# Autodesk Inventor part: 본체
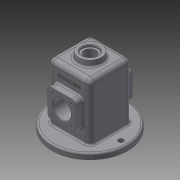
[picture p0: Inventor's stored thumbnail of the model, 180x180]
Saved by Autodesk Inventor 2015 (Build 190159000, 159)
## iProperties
Created: 2021-08
Part Number: 본체
Material: 일반
Document SubType Name: Modeling
Designer: 10415
Density: 1 g/cm^3
Appearance: 기본값
Author: 10415
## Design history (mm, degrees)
sketch "스케치1"
  geometry: C1 r 67 at (0, 0); 1 further point
  constraints: 1 centre point, 1 coincident
  dimensions: "d0" = 134 diameter of C1
extrude "돌출1" new body sketch "스케치1" distance "d1" = 10; taper "d2" = 0 deg
sketch "스케치2"
  geometry: L1 (37, -37)-(-37, -37); L2 (-37, -37)-(-37, 37); L3 (-37, 37)-(37, 37); L4 (37, 37)-(37, -37); L5 (37, -37)-(-37, 37); L6 (-37, -37)-(37, 37); C1 r 67 at (0, 0) reference
  constraints: 12 end point, 2 midpoint, 2 parallel, 1 horizontal, 1 perpendicular
  dimensions: "d3" = 74 distance of L3.end L1.start; "d4" = 74 distance of L2.end L3.end
extrude "돌출2" join sketch "스케치2" distance "d5" = 100; taper "d6" = 0 deg
sketch "스케치3"
  geometry: L1 (32, -32)-(-32, -32); L2 (-32, -32)-(-32, 32); L3 (-32, 32)-(32, 32); L4 (32, 32)-(32, -32); L5 (32, -32)-(-32, 32); L6 (-32, -32)-(32, 32); C1 r 67 at (0, 0) reference
  constraints: 12 end point, 2 midpoint, 2 parallel, 1 horizontal, 1 perpendicular
  dimensions: "d7" = 64 distance of L1.end L2.end; "d8" = 64 distance of L2.end L3.end
extrude "돌출3" cut sketch "스케치3" distance "d9" = 105; taper "d10" = 0 deg
fillet "모깎기2" dims "d27" = 3
node "작업 평면1"
sketch "스케치7"
  geometry: C1 r 20 at (0, 0); 1 further point
  constraints: 1 centre point, 1 coincident
  dimensions: "d29" = 40 diameter of C1
extrude "돌출6" join sketch "스케치7" stored distance "d30" = 13; taper "d31" = 6 deg
sketch "스케치8"
  geometry: C1 r 20 at (0, 0) reference; C2 r 14 at (0, 0)
  constraints: 1 centre point, 1 coincident
  dimensions: "d32" = 28 diameter of C2
extrude "돌출7" cut sketch "스케치8" distance "d33" = 4; taper "d34" = 0 deg
sketch "스케치9"
  geometry: C1 r 14 at (0, 0) reference; C2 r 10.5 at (0, 0)
  constraints: 1 centre point, 1 coincident
  dimensions: "d35" = 21 diameter of C2
extrude "돌출8" cut sketch "스케치9" stored distance "d36" = 4; taper "d37" = 0 deg
fillet "모깎기3" dims "d38" = 8
fillet "모깎기4" dims "d39" = 8
sketch "스케치12"
  geometry: L1 (-38, -10)-(96, -10) reference; C1 r 25 at (29, 45); 1 further point
  constraints: 1 centre point, 1 vertical alignment
  dimensions: "d56" = 50 diameter of C1; "d57" = 55 distance from line of L1 C1.centre
extrude "돌출11" join sketch "스케치12" distance "d58" = 13; taper "d60" = 0 deg; dims "d59" = 12, "d61" = 0
chamfer "모따기2" distance "d62" = 7; stored, may be unused: second distance "d63" = 2, angle "d64" = 20 deg
sketch "스케치13"
  geometry: L1 (-25, -25)-(25, -25); L2 (25, -25)-(25, 25); L3 (25, 25)-(-25, 25); L4 (-25, 25)-(-25, -25); L5 (-25, -25)-(25, 25); L6 (25, -25)-(-25, 25); C1 r 25 at (0, 0) reference; 1 further point
  constraints: 12 end point, 2 midpoint, 2 parallel, 1 horizontal, 1 perpendicular
  dimensions: "d65" = 50 distance of L2.end L3.end; "d66" = 50 distance of L1.end L2.end
extrude "돌출12" join sketch "스케치13" distance "d67" = 13; taper "d68" = 0 deg
sketch "스케치14"
  geometry: L1 (-38, -10)-(96, -10) reference; C1 r 16 at (29, 45); 1 further point
  constraints: 1 centre point, 1 vertical alignment
  dimensions: "d69" = 32 diameter of C1; "d70" = 55 distance from line of L1 C1.centre
extrude "돌출13" cut sketch "스케치14" stored distance "d71" = 13; taper "d72" = 0 deg
fillet "모깎기5" dims "d73" = 8
fillet "모깎기6" dims "d74" = 3
sketch "스케치15"
  geometry: A1 r 8 centre (12, 28) between (4, 28) and (12, 20) reference; A2 r 8 centre (46, 28) between (46, 20) and (54, 28) reference; A3 r 8 centre (46, 62) between (54, 62) and (46, 70) reference; A4 r 8 centre (12, 62) between (12, 70) and (4, 62) reference; 1 further point
hole "구멍2" sketch "스케치15" at (12, 62), (12, 28), (46, 62), (46, 28) diameter "d75" = 3.242; stored, may be unused: countersink angle "d79" = 90 deg, drill point angle "d81" = 118 deg; dims "d76" = 8, "d77" = 4, "d78" = 2, "d80" = 10
fillet "모깎기7" dims "d82" = 3
chamfer "모따기3" distance "d83" = 1; stored, may be unused: second distance "d84" = 2, angle "d85" = 20 deg
fillet "모깎기8" dims "d86" = 3
fillet "모깎기9" dims "d87" = 3
sketch "스케치16"
  geometry: C1 r 64 at (0, 0) reference; A1 r 55 centre (0, 0) between (-55, 0) and (55, 0)
  constraints: 2 point on circle, 1 centre point, 1 coincident
  dimensions: "d88" = 110 diameter of A1
hole "구멍3" sketch "스케치16" at (-55, 0), (55, 0) diameter "d89" = 9; stored, may be unused: countersink angle "d93" = 90 deg, drill point angle "d95" = 0 deg; dims "d90" = 9, "d91" = 4, "d92" = 2, "d94" = 10
fillet "모깎기10" dims "d96" = 3
chamfer "모따기4" distance "d97" = 1; stored, may be unused: second distance "d98" = 2, angle "d99" = 20 deg
sketch "스케치17"
  geometry: L1 (9, 18)-(49, 18) reference; L2 (-8, 0)-(-8, -89) reference; 2 further points
  constraints: 1 other
  dimensions: "d100" = 28 distance from line of point (29, -10) L1; "d101" = 37 distance from line of L2 point (29, -10)
feature "엠보싱1" sketch "스케치17" dims "d7" = 64, "d8" = 64, "d102" = 0.5, "d103" = 0
node "솔리드1"
mirror "대칭2"
mirror "대칭3"
